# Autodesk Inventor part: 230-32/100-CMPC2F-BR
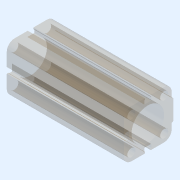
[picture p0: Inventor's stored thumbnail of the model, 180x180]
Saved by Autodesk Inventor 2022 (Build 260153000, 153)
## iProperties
Category: PARTsolutions
Company: METALWORK
Part Number: 230-32/100-CMPC2F-BR
Material: Generico
Catalog Web Link: www.cadenas.de
Description: CMPC2F-BR-
Vendor: METALWORK
Document SubType Name: Modeling
Designer: partserver
Manufacturer: METALWORK
Mass: 125 g
Surface Area: 499.75 cm^2
Volume: 125 cm^3
Density: 1 g/cm^3
Appearance: Policarbonato - Fumé
PSOL_IDENT_0: {$CADENAS_DATA\23d-libs\metalwork\actuators\comp_cyl_ser_cmpc_2_flat\parts\cmpc_2_flat_barrel.prj},2
PSOL_IDENT_1: 02 {VTYP=3D},{NB=230-32/100-CMPC2F-BR},{LINA=230-32/100-CMPC2F-BR},{NN=CMPC2F-BR},{DATE=18.06.2021 0
PSOL_IDENT_2: 8:06:07},{GEOMDATE=26.11.2009 08:27:00},{VERSION=},{LINEID=50},{WBVAR=TYPE,VE,HUB},{WBNUMERIC=TYPE,H
PSOL_IDENT_3: UB}  {NB=230-32/100-CMPC2F-BR},{LINA=230-32/100-CMPC2F-BR},{KT=DUMMY},{IDNR=},{TYPE=23},{VE=0},{HUB=
PSOL_IDENT_4: 100},{DI=32},{A=47.000},{B=32.250},{BB=32.250},{B2=0.000},{D=48.500},{D1=9},{R1=7.500},{R2=0.500},{H
PSOL_IDENT_5: 1=6.950},{H2=5.350},{L1=3.550},{L2=1.550},{L3=10.000},{G=44.500},{HH=14.750},{C1=8.000}
NB: 230-32/100-CMPC2F-BR
NN: CMPC2F-BR
NBSYN: $TYPE.$VE.-$DI./$HUB.-CMPC2F-BR
LINA: 230-32/100-CMPC2F-BR
CATALOG: Metalwork
TYPE: Centre distance to UNITOP, male rod
VE: Double-acting
HUB: 100
DI: 32
A: 47
B: 32.25
BB: 32.25
B2: 0
D: 48.5
D1: 9
R1: 7.5
R2: 0.5
H1: 6.95
H2: 5.35
L1: 3.55
L2: 1.55
L3: 10
G: 44.5
HH: 14.75
C1: 8
SUPPLIER: METALWORK
ARTICLENO: 230-32/100-CMPC2F-BR
BOMINFO: 230-32/100-CMPC2F-BR
CREATOR: CADENAS GmbH
Title: 230-32/100-CMPC2F-BR
Author: Cadenas PARTsolutions
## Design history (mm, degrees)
sketch "Sketch_1"
  geometry: L1 (-23.5, 16)-(-23.5, 3.075); L2 (-23.1, 2.675)-(-22.15, 2.675); L3 (-21.95, 2.875)-(-21.95, 3.275); L4 (-21.75, 3.475)-(-18.6, 3.475); L5 (-18.4, 3.275)-(-18.4, -3.275); L6 (-18.6, -3.475)-(-21.75, -3.475); L7 (-21.95, -3.275)-(-21.95, -2.875); L8 (-22.15, -2.675)-(-23.1, -2.675); L9 (-23.5, -3.075)-(-23.5, -16); L10 (-16, -23.5)-(-3.075, -23.5); L11 (-2.675, -23.1)-(-2.675, -22.15); L12 (-2.875, -21.95)-(-3.275, -21.95); L13 (-3.475, -21.75)-(-3.475, -18.6); L14 (-3.275, -18.4)-(3.275, -18.4); L15 (3.475, -18.6)-(3.475, -21.75); L16 (3.275, -21.95)-(2.875, -21.95); L17 (2.675, -22.15)-(2.675, -23.1); L18 (3.075, -23.5)-(16, -23.5); L19 (23.5, -16)-(23.5, -10.786); L20 (23.871, -10.303)-(24.629, -10.099); L21 (25, -9.616)-(25, 9.616); L22 (24.629, 10.099)-(23.871, 10.303); L23 (23.5, 10.786)-(23.5, 16); L24 (16, 23.5)-(3.075, 23.5); L25 (2.675, 23.1)-(2.675, 22.15); L26 (2.875, 21.95)-(3.275, 21.95); L27 (3.475, 21.75)-(3.475, 18.6); L28 (3.275, 18.4)-(-3.275, 18.4); L29 (-3.475, 18.6)-(-3.475, 21.75); L30 (-3.275, 21.95)-(-2.875, 21.95); L31 (-2.675, 22.15)-(-2.675, 23.1); L32 (-3.075, 23.5)-(-16, 23.5); C1 r 4 at (-16.125, -16.125); C2 r 4 at (16.125, -16.125); C3 r 16 at (0, 0); C4 r 4 at (-16.125, 16.125); C5 r 4 at (16.125, 16.125); A1 r 7.5 centre (-16, 16) between (-16, 23.5) and (-23.5, 16); A2 r 0.4 centre (-23.1, 3.075) between (-23.5, 3.075) and (-23.1, 2.675); A3 r 0.2 centre (-22.15, 2.875) between (-22.15, 2.675) and (-21.95, 2.875); A4 r 0.2 centre (-21.75, 3.275) between (-21.75, 3.475) and (-21.95, 3.275); A5 r 0.2 centre (-18.6, 3.275) between (-18.4, 3.275) and (-18.6, 3.475); A6 r 0.2 centre (-18.6, -3.275) between (-18.6, -3.475) and (-18.4, -3.275); A7 r 0.2 centre (-21.75, -3.275) between (-21.95, -3.275) and (-21.75, -3.475); A8 r 0.2 centre (-22.15, -2.875) between (-21.95, -2.875) and (-22.15, -2.675); A9 r 0.4 centre (-23.1, -3.075) between (-23.1, -2.675) and (-23.5, -3.075); A10 r 7.5 centre (-16, -16) between (-23.5, -16) and (-16, -23.5); A11 r 0.4 centre (-3.075, -23.1) between (-3.075, -23.5) and (-2.675, -23.1); A12 r 0.2 centre (-2.875, -22.15) between (-2.675, -22.15) and (-2.875, -21.95); A13 r 0.2 centre (-3.275, -21.75) between (-3.475, -21.75) and (-3.275, -21.95); A14 r 0.2 centre (-3.275, -18.6) between (-3.275, -18.4) and (-3.475, -18.6); A15 r 0.2 centre (3.275, -18.6) between (3.475, -18.6) and (3.275, -18.4); A16 r 0.2 centre (3.275, -21.75) between (3.275, -21.95) and (3.475, -21.75); A17 r 0.2 centre (2.875, -22.15) between (2.875, -21.95) and (2.675, -22.15); A18 r 0.4 centre (3.075, -23.1) between (2.675, -23.1) and (3.075, -23.5); A19 r 7.5 centre (16, -16) between (16, -23.5) and (23.5, -16); A20 r 0.5 centre (24, -10.786) between (23.871, -10.303) and (23.5, -10.786); A21 r 0.5 centre (24.5, -9.616) between (24.629, -10.099) and (25, -9.616); A22 r 0.5 centre (24.5, 9.616) between (25, 9.616) and (24.629, 10.099); A23 r 0.5 centre (24, 10.786) between (23.5, 10.786) and (23.871, 10.303); A24 r 7.5 centre (16, 16) between (23.5, 16) and (16, 23.5); A25 r 0.4 centre (3.075, 23.1) between (3.075, 23.5) and (2.675, 23.1); A26 r 0.2 centre (2.875, 22.15) between (2.675, 22.15) and (2.875, 21.95); A27 r 0.2 centre (3.275, 21.75) between (3.475, 21.75) and (3.275, 21.95); A28 r 0.2 centre (3.275, 18.6) between (3.275, 18.4) and (3.475, 18.6); A29 r 0.2 centre (-3.275, 18.6) between (-3.475, 18.6) and (-3.275, 18.4); A30 r 0.2 centre (-3.275, 21.75) between (-3.275, 21.95) and (-3.475, 21.75); A31 r 0.2 centre (-2.875, 22.15) between (-2.875, 21.95) and (-2.675, 22.15); A32 r 0.4 centre (-3.075, 23.1) between (-2.675, 23.1) and (-3.075, 23.5); 5 further points
  constraints: 64 end point, 64 point on circle, 37 centre point
extrude "Extrusion1" join sketch "Sketch_1" distance "d0" = 115; taper "d1" = 0 deg
node "br_l_XY"
node "br_l_YZ"
node "br_l_ZX"
node "br_l_X"
node "br_l_Y"
node "br_l_Z"
node "br_l_Center"
node "br_r_XY"
node "br_r_YZ"
node "br_r_ZX"
node "br_r_X"
node "br_r_Y"
node "br_r_Z"
node "br_r_Center"
node "sensor_left_XY"
node "sensor_left_YZ"
node "sensor_left_ZX"
node "sensor_left_X"
node "sensor_left_Y"
node "sensor_left_Z"
node "sensor_left_Center"
node "sensor_right_XY"
node "sensor_right_YZ"
node "sensor_right_ZX"
node "sensor_right_X"
node "sensor_right_Y"
node "sensor_right_Z"
node "sensor_right_Center"
body "Solid1"
other parameters: "d2" = 0, "d3" = 0, "d4" = 0, "d5" = 0
